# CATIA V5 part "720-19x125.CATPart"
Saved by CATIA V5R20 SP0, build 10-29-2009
Part number: 720-19x125
Definition: NONE
Nomenclature: 720-19x125
Source: Unknown
Description: 720-19x125
Bounding box of the stored display mesh (mm): x 0 to 125, y -9.5 to 9.5, z -9.5 to 9.5
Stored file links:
  C:\Users\Utente\Desktop\IO LAVORO\3D X SITO CF\X SITO\720\720-19x125.CATPart
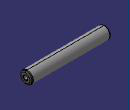
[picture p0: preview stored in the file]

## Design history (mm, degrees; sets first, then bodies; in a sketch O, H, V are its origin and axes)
Body1 "720-19x125" (main body)
  Solid1: solid without history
